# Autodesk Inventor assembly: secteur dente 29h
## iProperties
Author: chr
Created: 2002-03
Part Number: secteur dente 29h
Document SubType Name: Assemblage
Designer: chr
Control State: 0
Master: False
Checked Out: False
PropertySet Name: Design Tracking Control
Shininess: 41.0
Angle Display Precision: 2
Document Length Units: 11269
Document Angle Units: 11283
Document Time Units: 11279
Document Mass Units: 11290
Document Length Units Precision: 3
Document Angle Units Precision: 2
Compacted: False
PropertySet Name: _Private Model Information
Density: 0.0
Volumn: 0.0
Area: 0.0
PropertySet Name: Model Information
